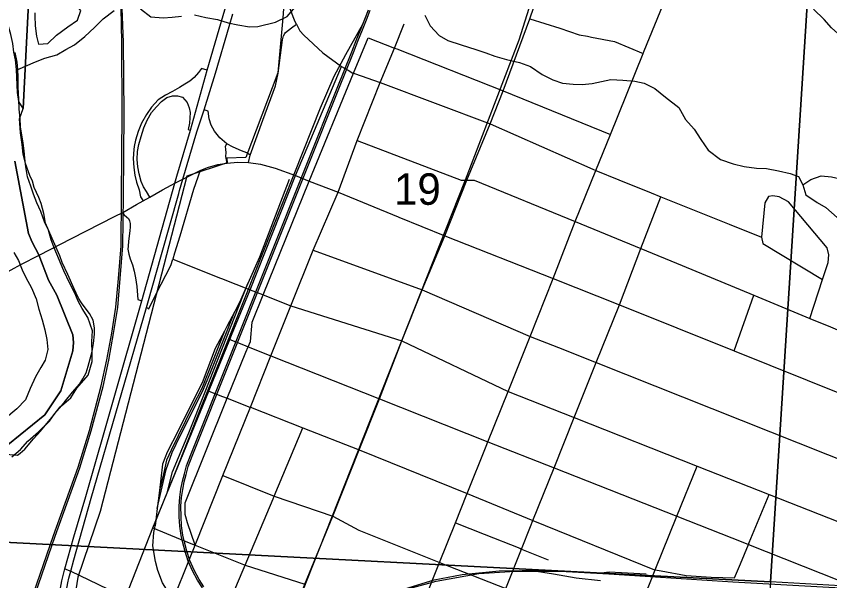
# Model space of a CAD drawing. Extents: x 0 to 42.5, y 0 to 22.
# Drawn here: x 2.441 to 2.982, y 20.015 to 20.39 of the extents above; entities that cross this region are included whole.
import ezdxf

# ---------------------------------------------------------------- set-up
doc = ezdxf.new("R2010")
doc.units = 0
for name, color, linetype in [('Default', 7, 'Continuous'), ('GM_X_City_Street', 7, 'Continuous'), ('GM_X_County_Road', 7, 'Continuous'), ('GM_X_Interchange_Ramps', 7, 'Continuous'), ('GM_X_Major_River', 7, 'Continuous'), ('GM_X_Minor_Lake', 7, 'Continuous'), ('GM_X_Minor_River', 7, 'Continuous'), ('GM_X_Rail_Line', 7, 'Continuous'), ('GM_X_Section', 7, 'Continuous'), ('GM_X_Section_Text', 7, 'Continuous'), ('GM_X_State_Route', 7, 'Continuous'), ('GM_X_Township_Road', 7, 'Continuous'), ('GM_X_US_Route', 7, 'Continuous')]:
    doc.layers.add(name, color=color, linetype=linetype)

msp = doc.modelspace()

# ---------------------------------------------------------------- linework, layer by layer
at = {"layer": 'Default'}
msp.add_lwpolyline([(2.62824, 20.5324), (2.61795, 20.38924), (2.61459, 20.35269), (2.59324, 20.29641), (2.58058, 20.29596), (2.5808, 20.29284), (2.55409, 20.28385), (2.49643, 20.06079), (2.48148, 20.01708), (2.4779, 19.99463), (2.47674, 19.97464), (2.47365, 19.97047), (2.48265, 19.88106), (2.48572, 19.85498), (2.4955, 19.78591), (2.48027, 19.78644), (2.48045, 19.79071), (2.47477, 19.82321), (2.45491, 19.83113), (2.4401, 19.83517)], dxfattribs=at)
at = {"layer": 'GM_X_City_Street'}
for p, q in [((2.76442, 20.3406), (2.83574, 20.31171)), ((2.91476, 20.25195), (2.93636, 20.24325)), ((2.91805, 20.1677), (2.9312, 20.20467)), ((2.58261, 20.17519), (2.59166, 20.1716)), ((2.5686, 20.14094), (2.57771, 20.13738)), ((2.55, 20.04225), (2.55952, 20.03838)), ((2.91833, 20.01667), (2.92225, 20.02606)), ((2.58357, 20.00304), (2.59151, 20.02195))]:
    msp.add_line(p, q, dxfattribs=at)
for points in [[(2.68271, 20.34614), (2.69208, 20.36916), (2.69862, 20.38525)], [(2.78224, 20.38866), (2.80203, 20.38245), (2.81494, 20.37804), (2.8205, 20.37698), (2.82328, 20.37645), (2.83844, 20.37347), (2.85754, 20.36546)], [(2.63538, 20.28068), (2.66492, 20.35237), (2.67464, 20.37595)], [(2.67464, 20.37595), (2.69208, 20.36916), (2.69366, 20.36854), (2.76442, 20.3406)], [(2.53134, 20.04984), (2.5686, 20.14094), (2.56882, 20.14148), (2.58261, 20.17519), (2.58382, 20.17813), (2.59618, 20.20832), (2.62639, 20.28429), (2.65691, 20.35683)], [(2.7559, 20.31879), (2.82401, 20.28848), (2.82599, 20.28769), (2.84129, 20.28153), (2.8629, 20.27283), (2.86927, 20.27026), (2.91476, 20.25195)], [(2.55952, 20.03838), (2.55434, 20.05326), (2.55326, 20.05728), (2.55286, 20.05879), (2.55292, 20.06658), (2.58085, 20.13615), (2.59315, 20.16679), (2.59481, 20.17034), (2.59643, 20.1738), (2.59748, 20.18671), (2.60482, 20.20491), (2.63538, 20.28068)], [(2.84181, 20.19831), (2.85609, 20.23573), (2.86927, 20.27026)], [(2.96854, 20.18924), (2.97697, 20.21505), (2.98066, 20.22636), (2.98108, 20.23149), (2.97997, 20.23625), (2.9542, 20.26686), (2.94815, 20.27014), (2.94379, 20.27094), (2.94093, 20.27039), (2.93844, 20.26623), (2.93636, 20.24325)], [(2.81226, 20.25384), (2.85609, 20.23573), (2.88357, 20.22437), (2.9312, 20.20467), (2.96854, 20.18924), (2.98229, 20.18355), (2.99304, 20.17911)], [(2.93636, 20.24325), (2.93709, 20.23906), (2.97697, 20.21505)], [(2.66941, 19.71242), (2.67075, 19.73668), (2.67165, 19.7558), (2.6737, 19.77389), (2.68595, 19.80563), (2.69885, 19.84064), (2.70415, 19.85392), (2.70704, 19.86117), (2.73245, 19.9249), (2.74078, 19.94577), (2.74791, 19.96367), (2.75666, 19.98562), (2.76616, 20.00945), (2.77667, 20.03581), (2.78265, 20.05079), (2.78428, 20.05487), (2.7983, 20.08982), (2.81171, 20.12327), (2.82637, 20.15983), (2.84181, 20.19831)], [(2.78246, 20.17728), (2.80118, 20.16984), (2.82637, 20.15983), (2.99982, 20.09096), (3.0146, 20.08509), (3.07622, 20.06062), (3.08382, 20.06075), (3.09625, 20.06663), (3.09672, 20.06685)], [(2.59166, 20.1716), (2.59481, 20.17034), (2.60994, 20.16433), (2.68209, 20.13566)], [(2.57771, 20.13738), (2.58085, 20.13615), (2.59591, 20.13027), (2.59625, 20.13014), (2.63122, 20.11649), (2.66875, 20.10184)], [(2.68209, 20.13566), (2.75435, 20.10716), (2.7983, 20.08982), (2.88006, 20.05757), (2.92377, 20.04033), (2.92757, 20.03884), (2.98761, 20.01516)], [(2.59151, 20.02195), (2.59286, 20.02516), (2.61136, 20.06922), (2.61208, 20.07092), (2.63122, 20.11649)], [(2.66875, 20.10184), (2.74051, 20.07266), (2.78428, 20.05487), (2.86503, 20.02204), (2.86562, 20.02194), (2.86944, 20.02125)], [(2.82893, 19.93139), (2.83701, 19.95133), (2.84245, 19.96477), (2.84746, 19.97713), (2.86221, 20.01352), (2.86562, 20.02194), (2.88006, 20.05757), (2.89359, 20.09095)], [(2.57804, 20.08464), (2.61208, 20.07092), (2.65111, 20.05768)], [(2.92225, 20.02606), (2.92757, 20.03884), (2.92812, 20.04015), (2.94143, 20.07208)], [(2.65111, 20.05768), (2.66836, 20.04833), (2.72173, 20.02711)], [(2.51295, 20.0031), (2.51314, 20.00356), (2.53134, 20.04984)], [(2.53134, 20.04984), (2.54952, 20.04245), (2.55, 20.04225)], [(2.73277, 20.05335), (2.75175, 20.04576), (2.77548, 20.03628), (2.77667, 20.03581), (2.79447, 20.0287)], [(2.72173, 20.02711), (2.72218, 20.02693), (2.76616, 20.00945), (2.76687, 20.00917)], [(2.86944, 20.02125), (2.88608, 20.01826), (2.90277, 20.01718), (2.91833, 20.01667)]]:
    msp.add_lwpolyline(points, dxfattribs=at)
at = {"layer": 'GM_X_County_Road'}
for p, q in [((2.6381, 20.23468), (2.71053, 20.20823)), ((2.71053, 20.20823), (2.78246, 20.17728)), ((2.54108, 19.99233), (2.55583, 20.02917))]:
    msp.add_line(p, q, dxfattribs=at)
for points in [[(2.62704, 20.385), (2.62612, 20.38657), (2.62517, 20.38874), (2.62271, 20.39522), (2.62168, 20.39876)], [(2.61923, 20.37877), (2.61972, 20.37954), (2.62368, 20.38262), (2.62704, 20.385)], [(2.62704, 20.385), (2.6291, 20.38071), (2.63187, 20.37777), (2.64441, 20.36603), (2.65691, 20.35683), (2.66129, 20.35434), (2.66452, 20.35251), (2.66492, 20.35237), (2.6656, 20.35213)], [(2.60457, 20.32112), (2.61292, 20.34397), (2.6147, 20.35242), (2.61754, 20.37474), (2.61826, 20.37723), (2.61923, 20.37877)], [(2.6656, 20.35213), (2.68271, 20.34614), (2.7559, 20.31879)], [(2.65461, 20.2733), (2.66731, 20.30767), (2.68271, 20.34614)], [(2.59495, 20.29312), (2.59605, 20.2978), (2.60457, 20.32112)], [(2.66731, 20.30767), (2.73658, 20.28115), (2.74035, 20.28127)], [(2.56281, 20.28777), (2.55851, 20.27501), (2.54927, 20.2441)], [(2.74035, 20.28127), (2.74514, 20.28133), (2.81226, 20.25384)], [(2.62326, 20.19762), (2.6381, 20.23468), (2.65461, 20.2733)], [(2.54927, 20.2441), (2.54588, 20.23277), (2.54468, 20.22873)], [(2.54485, 19.77772), (2.54527, 19.77918), (2.55935, 19.81862), (2.56315, 19.83049), (2.56924, 19.84953), (2.58386, 19.88659), (2.59718, 19.92035), (2.60469, 19.93941), (2.61336, 19.96139), (2.61599, 19.96805), (2.63252, 20.01248), (2.65111, 20.05768), (2.66875, 20.10184), (2.68209, 20.13566), (2.69704, 20.17433), (2.71053, 20.20823), (2.72563, 20.24413)], [(2.54468, 20.22873), (2.5487, 20.22705), (2.57577, 20.21637), (2.57716, 20.21582)], [(2.57716, 20.21582), (2.59618, 20.20832), (2.60427, 20.20512), (2.60482, 20.20491)], [(2.60482, 20.20491), (2.62326, 20.19762), (2.69704, 20.17433)], [(2.55583, 20.02917), (2.55952, 20.03838), (2.57804, 20.08464), (2.59625, 20.13014), (2.60994, 20.16433), (2.62326, 20.19762)], [(2.69704, 20.17433), (2.76776, 20.14061), (2.81171, 20.12327), (2.89359, 20.09095), (2.94143, 20.07208), (3.00057, 20.04874), (3.04371, 20.03172)], [(2.55952, 20.03838), (2.59286, 20.02516), (2.63252, 20.01248)], [(2.47291, 20.02256), (2.47678, 20.02115), (2.51314, 20.00356), (2.54108, 19.99233)]]:
    msp.add_lwpolyline(points, dxfattribs=at)
at = {"layer": 'GM_X_Interchange_Ramps'}
msp.add_line((2.59605, 20.2978), (2.59401, 20.29951), dxfattribs=at)
for points in [[(2.5675, 20.35448), (2.56373, 20.35558), (2.56174, 20.35296), (2.55878, 20.34965), (2.556, 20.34722), (2.55278, 20.34522), (2.54912, 20.34287), (2.54451, 20.34034), (2.5399, 20.33791), (2.53502, 20.33469), (2.5305, 20.32973), (2.5271, 20.32494), (2.52389, 20.31911), (2.52162, 20.31354), (2.51988, 20.30797), (2.51907, 20.30374)], [(2.52928, 20.26986), (2.52719, 20.27377), (2.52519, 20.2769), (2.52362, 20.2803), (2.52232, 20.28543), (2.52136, 20.29004), (2.52101, 20.295), (2.52119, 20.30023), (2.52206, 20.30501), (2.52354, 20.31041), (2.52536, 20.31606), (2.52771, 20.32128), (2.53059, 20.32624), (2.53372, 20.33007), (2.5372, 20.33355), (2.54077, 20.33616), (2.54451, 20.33738), (2.54773, 20.33738), (2.55117, 20.33655), (2.5543, 20.33298), (2.55562, 20.32938), (2.55627, 20.32639), (2.55602, 20.3227), (2.55581, 20.31913), (2.55499, 20.31491), (2.55652, 20.3145)], [(2.59401, 20.29951), (2.59033, 20.30073), (2.58477, 20.30321), (2.5806, 20.30554), (2.57599, 20.30942), (2.57244, 20.31396), (2.57022, 20.31782), (2.5688, 20.32201), (2.56819, 20.3272), (2.56553, 20.32798)], [(2.58091, 20.29257), (2.57986, 20.29698), (2.58011, 20.29958), (2.58004, 20.30164), (2.57966, 20.30387), (2.5806, 20.30554)], [(2.51907, 20.30374), (2.51866, 20.30162), (2.5184, 20.29561), (2.51884, 20.28961), (2.51945, 20.28465), (2.52049, 20.27986), (2.52223, 20.27473), (2.52328, 20.2702), (2.52494, 20.26756)], [(2.43951, 20.29386), (2.4486, 20.24569), (2.45103, 20.23998), (2.45562, 20.23158), (2.46205, 20.21482), (2.46749, 20.20471), (2.47813, 20.17823), (2.47867, 20.17328), (2.47825, 20.16777), (2.47013, 20.14103), (2.45962, 20.12513), (2.4183, 20.09176)], [(2.4183, 20.09176), (2.45962, 20.12513), (2.47013, 20.14103), (2.47825, 20.16777), (2.47867, 20.17328), (2.47813, 20.17823), (2.46749, 20.20471), (2.46205, 20.21482), (2.45562, 20.23158), (2.45103, 20.23998), (2.4486, 20.24569), (2.43951, 20.29386)], [(2.5114, 20.25978), (2.51241, 20.25808), (2.51411, 20.25674), (2.51521, 20.25572), (2.51586, 20.25413), (2.51622, 20.25249), (2.51638, 20.25021), (2.51605, 20.24765), (2.51511, 20.24067), (2.51493, 20.23724), (2.51479, 20.23532), (2.51537, 20.23208), (2.51641, 20.22899), (2.51787, 20.22492), (2.51899, 20.22069), (2.51995, 20.21636), (2.52071, 20.21041), (2.5214, 20.20178), (2.5241, 20.20088)], [(2.53369, 20.20551), (2.54338, 20.22449), (2.54468, 20.22873)], [(2.52726, 20.19648), (2.5287, 20.19573), (2.53369, 20.20551)]]:
    msp.add_lwpolyline(points, dxfattribs=at)
at = {"layer": 'GM_X_Major_River'}
for points in [[(2.43755, 20.09719), (2.44326, 20.10209), (2.44822, 20.10757), (2.45527, 20.1138), (2.4627, 20.12078), (2.46614, 20.12608), (2.47072, 20.13118), (2.47682, 20.13646), (2.48084, 20.1429), (2.48847, 20.15159), (2.49099, 20.1607), (2.49102, 20.16583), (2.49088, 20.17381), (2.4913, 20.18103), (2.48813, 20.18998), (2.48438, 20.1959), (2.48175, 20.20067), (2.47951, 20.206), (2.47595, 20.21287), (2.47221, 20.22087), (2.46567, 20.23612), (2.46381, 20.24164), (2.46195, 20.24792), (2.45934, 20.25345), (2.45691, 20.26031), (2.45411, 20.26622), (2.45206, 20.27193), (2.45019, 20.27727), (2.44796, 20.28355), (2.44686, 20.29002), (2.44633, 20.29592), (2.44579, 20.30086), (2.44506, 20.306), (2.44415, 20.31113), (2.44342, 20.31684), (2.44308, 20.32235), (2.44255, 20.32844), (2.44221, 20.33509), (2.44169, 20.34289), (2.44173, 20.34973), (2.44157, 20.35486), (2.44103, 20.3598), (2.43974, 20.36627)], [(2.43894, 20.23306), (2.44213, 20.22772), (2.44436, 20.22162), (2.44698, 20.21647), (2.45073, 20.20961), (2.45372, 20.20237), (2.45557, 20.19551), (2.4578, 20.18828), (2.45947, 20.18161), (2.46095, 20.17514), (2.46148, 20.16868), (2.45973, 20.16147), (2.45685, 20.15655), (2.45322, 20.1503), (2.44976, 20.14272), (2.44668, 20.13514), (2.44096, 20.12909), (2.43277, 20.12211)]]:
    msp.add_lwpolyline(points, dxfattribs=at)
at = {"layer": 'GM_X_Minor_Lake'}
msp.add_lwpolyline([(2.45298, 20.39261), (2.45297, 20.39071), (2.45311, 20.38405), (2.45402, 20.37701), (2.45531, 20.37169), (2.46157, 20.37222), (2.46729, 20.37769), (2.4749, 20.38334), (2.48118, 20.38767), (2.48349, 20.39412), (2.4786, 20.39966), (2.47369, 20.40197), (2.47198, 20.40205)], dxfattribs=at)
at = {"layer": 'GM_X_Minor_River'}
for points in [[(2.55908, 20.39116), (2.56665, 20.38959), (2.57441, 20.38821), (2.58141, 20.38589), (2.58785, 20.38471), (2.5958, 20.38333), (2.60129, 20.38348), (2.61306, 20.38644), (2.62066, 20.3902), (2.62639, 20.39662)], [(2.44157, 20.35486), (2.45335, 20.35992), (2.45943, 20.36235), (2.46759, 20.36476), (2.47348, 20.36815), (2.47938, 20.37134), (2.48623, 20.37681), (2.49252, 20.38285), (2.49843, 20.3887), (2.50566, 20.39417)], [(2.5231, 20.3952), (2.53008, 20.39002), (2.53823, 20.38921), (2.54429, 20.38974), (2.55036, 20.39046)], [(2.71239, 20.39113), (2.71594, 20.38388), (2.72197, 20.37757), (2.72764, 20.3743), (2.73652, 20.37121), (2.74617, 20.36829), (2.75298, 20.36597), (2.75884, 20.36384), (2.7666, 20.36151), (2.7753, 20.35955), (2.78268, 20.35685), (2.79041, 20.35167), (2.79759, 20.34801), (2.80383, 20.34588), (2.81103, 20.34507), (2.8169, 20.34484), (2.82373, 20.34556), (2.8298, 20.34685), (2.83606, 20.34833), (2.84402, 20.3479), (2.85198, 20.34709), (2.85822, 20.34591), (2.8654, 20.34225), (2.87238, 20.3365), (2.88124, 20.3296), (2.88574, 20.32159), (2.89158, 20.31528), (2.8959, 20.30841), (2.90078, 20.30116), (2.90908, 20.29503), (2.9174, 20.29212), (2.92478, 20.29036), (2.93292, 20.28917), (2.93956, 20.28894), (2.94751, 20.28756), (2.95527, 20.28561), (2.96094, 20.28367), (2.96375, 20.27814), (2.96579, 20.27147), (2.97334, 20.26648), (2.97901, 20.26303), (2.98673, 20.25633)], [(2.96375, 20.27814), (2.96908, 20.28171), (2.97591, 20.28414), (2.98292, 20.28353), (2.98954, 20.28196), (2.99693, 20.28192), (3.0021, 20.29043), (3.0029, 20.29651), (3.00446, 20.30486), (3.00511, 20.31702), (3.00515, 20.32348), (3.00405, 20.3309), (3.00315, 20.33889), (3.00225, 20.34612), (3.00098, 20.35487), (2.99875, 20.36305), (2.995, 20.36973), (2.99106, 20.37526), (2.98276, 20.38254), (2.97806, 20.38808), (2.9709, 20.39497)]]:
    msp.add_lwpolyline(points, dxfattribs=at)
at = {"layer": 'GM_X_Rail_Line'}
for p, q in [((2.53571, 20.0748), (2.53431, 20.06279)), ((2.53431, 20.06279), (2.53297, 20.05125)), ((2.82817, 20.01973), (2.86072, 20.01787))]:
    msp.add_line(p, q, dxfattribs=at)
for points in [[(2.61877, 19.97568), (2.63365, 20.01431), (2.73943, 20.28157), (2.77508, 20.37465), (2.82907, 20.5454), (2.87376, 20.74288), (2.88102, 20.77215), (2.88062, 20.78804), (2.87833, 20.80114), (2.86963, 20.83794), (2.85559, 20.89316), (2.85359, 20.9)], [(2.43474, 19.95037), (2.44159, 19.97222), (2.44877, 19.99295), (2.46637, 20.04439), (2.48291, 20.0898), (2.49039, 20.1144), (2.49827, 20.14405), (2.50204, 20.16147), (2.5053, 20.17914), (2.50805, 20.19656), (2.50967, 20.21576), (2.51143, 20.2376), (2.51185, 20.27032), (2.51225, 20.32565), (2.51186, 20.37315), (2.50974, 20.4295)], [(2.44046, 19.97259), (2.44764, 19.99334), (2.46524, 20.04478), (2.48177, 20.09018), (2.48924, 20.11473), (2.49711, 20.14433), (2.50087, 20.1617), (2.50412, 20.17934), (2.50686, 20.1967), (2.50848, 20.21585), (2.51023, 20.23766), (2.51065, 20.27033), (2.51105, 20.32565), (2.51066, 20.37313), (2.50973, 20.43078)], [(2.56436, 20.00989), (2.56118, 20.01498), (2.55785, 20.02127), (2.55498, 20.02764), (2.55286, 20.03415), (2.55128, 20.04001), (2.55022, 20.04472), (2.54927, 20.05104), (2.54895, 20.05734), (2.5489, 20.06425), (2.54927, 20.0703), (2.55006, 20.0756), (2.55107, 20.0809), (2.55239, 20.08575), (2.55381, 20.09108), (2.55645, 20.09809), (2.63378, 20.292), (2.654, 20.34248), (2.66372, 20.36656), (2.66664, 20.37408), (2.66968, 20.38166), (2.67234, 20.38829), (2.67478, 20.39467)], [(2.56535, 20.01056), (2.56222, 20.01558), (2.55892, 20.0218), (2.5561, 20.02807), (2.55401, 20.03449), (2.55245, 20.04029), (2.5514, 20.04494), (2.55046, 20.05116), (2.55015, 20.05738), (2.55009, 20.06422), (2.55046, 20.07018), (2.55124, 20.0754), (2.55224, 20.08063), (2.55354, 20.08544), (2.55495, 20.09071), (2.55757, 20.09766), (2.6349, 20.29156), (2.65512, 20.34203), (2.66483, 20.36612), (2.66776, 20.37364), (2.67079, 20.38122), (2.67346, 20.38785), (2.67591, 20.39428)], [(2.54087, 20.07323), (2.54911, 20.09366), (2.56348, 20.13023), (2.57753, 20.16482), (2.59359, 20.20548), (2.61036, 20.24741), (2.62586, 20.28626), (2.64296, 20.32944), (2.6521, 20.3504), (2.65978, 20.36481), (2.67107, 20.38513)], [(2.62203, 20.2817), (2.60235, 20.23), (2.59455, 20.21243)], [(2.54087, 20.07323), (2.54456, 20.08713), (2.55523, 20.11321), (2.56615, 20.14048), (2.59455, 20.21243)], [(2.59455, 20.21243), (2.58896, 20.19982), (2.58589, 20.19393)], [(2.53431, 20.06279), (2.54028, 20.08865), (2.54422, 20.10008), (2.54959, 20.11119), (2.56449, 20.14072), (2.56922, 20.15223), (2.57909, 20.17658), (2.58589, 20.19393)], [(2.58589, 20.19393), (2.58072, 20.18399), (2.57907, 20.18087)], [(2.57907, 20.18087), (2.57295, 20.16927), (2.5642, 20.14649), (2.55923, 20.1368), (2.54826, 20.11451), (2.5409, 20.10018), (2.53776, 20.09229), (2.53661, 20.08251), (2.53571, 20.0748)], [(2.57907, 20.18087), (2.56402, 20.1427), (2.55778, 20.13057), (2.54352, 20.10158), (2.54047, 20.09489), (2.53877, 20.08668), (2.53571, 20.0748)], [(2.53297, 20.05125), (2.53393, 20.0556), (2.5398, 20.07057), (2.54087, 20.07323)], [(2.80043, 19.89458), (2.73575, 19.91948), (2.69333, 19.93619), (2.63794, 19.95803), (2.59221, 19.9761), (2.56538, 19.9865), (2.55534, 19.99279), (2.54721, 19.99923), (2.54272, 20.00549), (2.53777, 20.01341), (2.53463, 20.02148), (2.53324, 20.02757), (2.53147, 20.03792), (2.53199, 20.04684), (2.53297, 20.05125)], [(2.61877, 19.97568), (2.65326, 19.99211), (2.69136, 20.00655), (2.71989, 20.01446), (2.74816, 20.0195), (2.77247, 20.02118), (2.80231, 20.02106), (2.83481, 20.01941), (2.91733, 20.01403), (3.26401, 19.99461), (3.61724, 19.97619), (3.94708, 19.95463), (4.29937, 19.93411), (4.5956, 19.91226), (5.05555, 19.8842), (5.17532, 19.87894), (5.25442, 19.87492), (5.30129, 19.87455), (5.33367, 19.88019), (5.36925, 19.89196), (5.40278, 19.90809), (5.43829, 19.93181), (5.47396, 19.96523), (5.54064, 20.03224)], [(2.68025, 20.00247), (2.68131, 20.00293), (2.7018, 20.01012), (2.71848, 20.01525), (2.73724, 20.01895), (2.7617, 20.02139), (2.77702, 20.02159), (2.78369, 20.02143)], [(2.78369, 20.02143), (2.79784, 20.01931), (2.81305, 20.01659), (2.82912, 20.0149)], [(2.78369, 20.02143), (2.81012, 20.02077), (2.82817, 20.01973)], [(2.82817, 20.01973), (2.83486, 20.02074), (2.85968, 20.01939)]]:
    msp.add_lwpolyline(points, dxfattribs=at)
at = {"layer": 'GM_X_Section'}
for points in [[(2.45631, 20.54783), (2.44523, 20.32894), (2.44222, 20.33369), (2.4413, 20.33956), (2.44062, 20.35491), (2.44008, 20.36135), (2.43896, 20.36647), (2.43824, 20.37215), (2.43694, 20.37822), (2.43414, 20.38808), (2.43041, 20.39947)], [(2.43125, 20.09926), (2.44128, 20.09827), (2.44318, 20.09959), (2.44622, 20.10222), (2.45194, 20.1092), (2.4567, 20.11429), (2.46413, 20.12335), (2.46984, 20.13033), (2.47232, 20.13335), (2.47803, 20.14014), (2.4828, 20.1458), (2.4849, 20.14901), (2.487, 20.15298), (2.48835, 20.15751), (2.49104, 20.16716), (2.49202, 20.17265), (2.49261, 20.17889), (2.49263, 20.18306), (2.49171, 20.18799), (2.48927, 20.19255), (2.48626, 20.19635), (2.484, 20.19958), (2.48193, 20.20281), (2.47912, 20.20888), (2.47481, 20.21857), (2.47106, 20.22654), (2.46957, 20.2309), (2.46432, 20.24248), (2.46001, 20.25273), (2.45891, 20.25898), (2.45704, 20.26562), (2.45555, 20.26961), (2.45255, 20.27644), (2.45125, 20.28061), (2.44956, 20.28441), (2.44675, 20.29237), (2.44508, 20.29863), (2.44435, 20.30508), (2.44325, 20.31266), (2.44273, 20.32213), (2.44523, 20.32894), (2.45631, 20.54783)], [(2.97397, 20.51334), (2.94222, 20.01405), (2.42774, 20.04057)]]:
    msp.add_lwpolyline(points, dxfattribs=at)
for points in [[(2.97397, 20.51334), (3.48334, 20.48855), (3.4546, 19.98469), (2.94222, 20.01405)], [(2.94222, 20.01405), (2.90759, 19.50738), (2.39595, 19.53408), (2.42774, 20.04057)]]:
    msp.add_lwpolyline(points, close=True, dxfattribs=at)
at = {"layer": 'GM_X_State_Route'}
for p, q in [((2.65461, 20.2733), (2.69451, 20.25684)), ((2.52043, 20.26497), (2.52494, 20.26756)), ((2.52494, 20.26756), (2.52928, 20.26986)), ((2.5114, 20.25978), (2.52043, 20.26497)), ((2.50632, 20.2572), (2.5114, 20.25978)), ((2.72563, 20.24413), (2.7976, 20.2158))]:
    msp.add_line(p, q, dxfattribs=at)
for points in [[(2.72563, 20.24413), (2.74035, 20.28127), (2.7559, 20.31879), (2.76442, 20.3406), (2.78224, 20.38866), (2.79714, 20.43215)], [(2.58091, 20.29257), (2.58772, 20.29315), (2.59495, 20.29312)], [(2.59495, 20.29312), (2.60294, 20.29185), (2.61286, 20.28932), (2.62639, 20.28429)], [(2.54356, 20.2779), (2.54599, 20.27918), (2.55134, 20.28193), (2.56281, 20.28777)], [(2.56281, 20.28777), (2.56781, 20.28968), (2.57472, 20.29158), (2.58091, 20.29257)], [(2.62639, 20.28429), (2.63538, 20.28068), (2.65461, 20.2733)], [(2.52928, 20.26986), (2.53772, 20.27481), (2.54356, 20.2779)], [(2.43069, 20.21808), (2.44365, 20.22508), (2.45573, 20.23131), (2.47736, 20.24246), (2.50632, 20.2572)], [(2.69451, 20.25684), (2.69495, 20.25665), (2.72563, 20.24413)], [(2.7976, 20.2158), (2.84181, 20.19831), (2.91805, 20.1677), (2.99048, 20.13861), (3.0278, 20.11926)]]:
    msp.add_lwpolyline(points, dxfattribs=at)
at = {"layer": 'GM_X_Township_Road'}
for points in [[(2.85827, 20.36727), (2.8724, 20.40211), (2.88646, 20.43676), (2.89554, 20.45915), (2.90528, 20.48314), (2.91553, 20.50841), (2.91962, 20.51852), (2.92257, 20.52577), (2.92622, 20.53468), (2.92741, 20.54473), (2.92561, 20.59848)], [(2.7976, 20.2158), (2.81226, 20.25384), (2.82599, 20.28769), (2.83574, 20.31171), (2.85754, 20.36546), (2.85827, 20.36727)], [(2.75314, 20.10416), (2.75435, 20.10716), (2.76776, 20.14061), (2.78246, 20.17728), (2.7976, 20.2158)], [(2.74036, 20.07227), (2.74051, 20.07266), (2.75314, 20.10416)], [(2.68554, 19.93558), (2.68788, 19.94141), (2.69687, 19.96382), (2.70382, 19.98115), (2.72218, 20.02693), (2.73277, 20.05335), (2.74036, 20.07227)]]:
    msp.add_lwpolyline(points, dxfattribs=at)
at = {"layer": 'GM_X_US_Route'}
for p, q in [((2.65461, 20.2733), (2.69451, 20.25684)), ((2.52043, 20.26497), (2.52494, 20.26756)), ((2.52494, 20.26756), (2.52928, 20.26986)), ((2.5114, 20.25978), (2.52043, 20.26497)), ((2.50632, 20.2572), (2.5114, 20.25978)), ((2.72563, 20.24413), (2.7976, 20.2158))]:
    msp.add_line(p, q, dxfattribs=at)
for points in [[(2.48683, 19.78349), (2.47872, 19.84567), (2.4717, 19.89743), (2.46666, 19.9368), (2.46578, 19.94985), (2.46534, 19.96334), (2.46567, 19.97913), (2.46709, 19.99262), (2.46936, 20.00598), (2.4709, 20.01464), (2.47291, 20.02256), (2.47883, 20.04383), (2.48673, 20.07075), (2.5241, 20.20088), (2.54599, 20.27918), (2.54732, 20.28393), (2.55652, 20.3145), (2.5675, 20.35448), (2.60208, 20.47298)], [(2.54918, 20.27445), (2.55134, 20.28193), (2.5607, 20.31338), (2.56553, 20.32798), (2.5731, 20.35242), (2.58217, 20.38353), (2.58464, 20.39198)], [(2.58091, 20.29257), (2.58772, 20.29315), (2.59495, 20.29312)], [(2.59495, 20.29312), (2.60294, 20.29185), (2.61286, 20.28932), (2.62639, 20.28429)], [(2.54356, 20.2779), (2.54599, 20.27918), (2.55134, 20.28193), (2.56281, 20.28777)], [(2.56281, 20.28777), (2.56781, 20.28968), (2.57472, 20.29158), (2.58091, 20.29257)], [(2.62639, 20.28429), (2.63538, 20.28068), (2.65461, 20.2733)], [(2.52928, 20.26986), (2.53772, 20.27481), (2.54356, 20.2779)], [(2.4756, 20.01649), (2.47678, 20.02115), (2.47881, 20.02863), (2.49047, 20.06962), (2.52726, 20.19648), (2.52813, 20.19955), (2.53724, 20.2319), (2.5486, 20.27246), (2.54918, 20.27445)], [(2.43069, 20.21808), (2.44365, 20.22508), (2.45573, 20.23131), (2.47736, 20.24246), (2.50632, 20.2572)], [(2.69451, 20.25684), (2.69495, 20.25665), (2.72563, 20.24413)], [(2.7976, 20.2158), (2.84181, 20.19831), (2.91805, 20.1677), (2.99048, 20.13861), (3.0278, 20.11926)], [(2.49321, 19.77755), (2.49308, 19.77852), (2.49221, 19.7848), (2.48431, 19.84687), (2.47707, 19.89995), (2.47247, 19.93811), (2.47071, 19.95742), (2.47027, 19.97562), (2.47115, 19.99075), (2.47324, 20.00457), (2.47477, 20.01323), (2.4756, 20.01649)]]:
    msp.add_lwpolyline(points, dxfattribs=at)

# ---------------------------------------------------------------- texts
at = {"layer": 'GM_X_Section_Text'}
msp.add_text('19', height=0.020928, rotation=0, dxfattribs=at).set_placement((2.69183, 20.26486))

doc.saveas('drawing.dxf')
